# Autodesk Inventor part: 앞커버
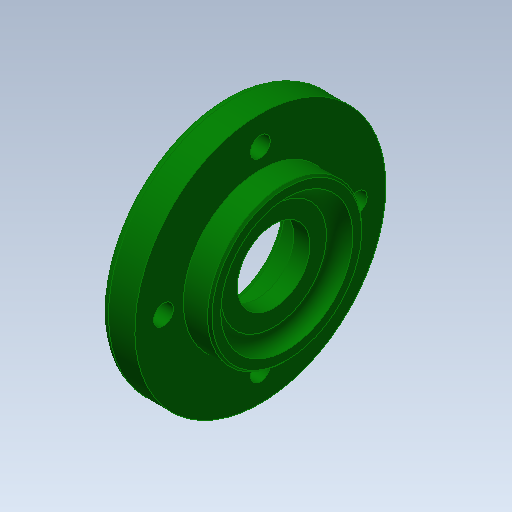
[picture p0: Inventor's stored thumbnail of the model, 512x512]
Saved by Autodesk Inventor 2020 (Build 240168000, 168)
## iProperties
Created: 2015-12
Part Number: 앞커버
Material: 알루미늄 6061
Document SubType Name: Modeling
Designer: mduedu
Density: 2.71 g/cm^3
Appearance: 진녹색
Author: mduedu
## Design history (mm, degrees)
sketch "스케치1"
  geometry: L1 (0, 0)-(14, 0); L2 (14, 0)-(14, 17.5); L3 (14, 17.5)-(8, 17.5); L4 (8, 17.5)-(8, 28.5); L5 (8, 28.5)-(0, 28.5); L6 (0, 28.5)-(0, 0)
  constraints: 12 end point, 4 parallel, 1 horizontal, 1 perpendicular
  dimensions: "d0" = 14 distance between parallel lines of L2 L6; "d2" = 8 distance of L4.end L5.end; "d3" = 57 diameter of L5 L1; "d4" = 35 diameter of L3 L1
revolve "회전1" sketch "스케치1" stored, may be unused: angle "d5" = 90 deg
hole "구멍1" diameter "d8" = 30; stored, may be unused: countersink angle "d12" = 90 deg, drill point angle "d14" = 0 deg; dims "d6" = 10, "d7" = 10, "d9" = 6, "d10" = 4, "d11" = 2, "d13" = 3
hole "구멍2" diameter "d17" = 25; stored, may be unused: countersink angle "d21" = 90 deg, drill point angle "d23" = 0 deg; dims "d15" = 10, "d16" = 10, "d18" = 6, "d19" = 4, "d20" = 2, "d22" = 7.3
hole "구멍3" diameter "d26" = 16.5; stored, may be unused: countersink angle "d30" = 90 deg, drill point angle "d32" = 0 deg; dims "d24" = 10, "d25" = 10, "d27" = 6, "d28" = 4, "d29" = 2, "d31" = 7.3
fillet "모깎기1" dims "d33" = 0.3
chamfer "모따기1" distance "d34" = 1; stored, may be unused: second distance "d35" = 2, angle "d36" = 30 deg
fillet "모깎기2" dims "d37" = 3
fillet "모깎기3" dims "d38" = 2
chamfer "모따기2" distance "d39" = 0.5; stored, may be unused: second distance "d40" = 2, angle "d41" = 45 deg
sketch "스케치2" dims "d42" = 42
  geometry: 9 further points
  constraints: 3 coincident, 2 vertical alignment, 9 other
  dimensions: "d46" = 360 deg dimension on point (0, 0) point (0, 21) (derived)
sketch "스케치3" dims "d57" = 44
  geometry: C1 r 13.077 at (0, 0) reference; C2 r 26.5 at (0, 0) reference; 5 further points
  constraints: 3 horizontal alignment, 1 coincident, 1 vertical alignment, 2 other
hole "구멍4" sketch "스케치3" at (-22, 0), (0, -22), (22, 0), (0, 22) diameter "d50" = 4.5; stored, may be unused: countersink angle "d54" = 90 deg, drill point angle "d56" = 0 deg; dims "d51" = 6, "d52" = 8, "d53" = 4.6, "d55" = 8
node "솔리드1"
